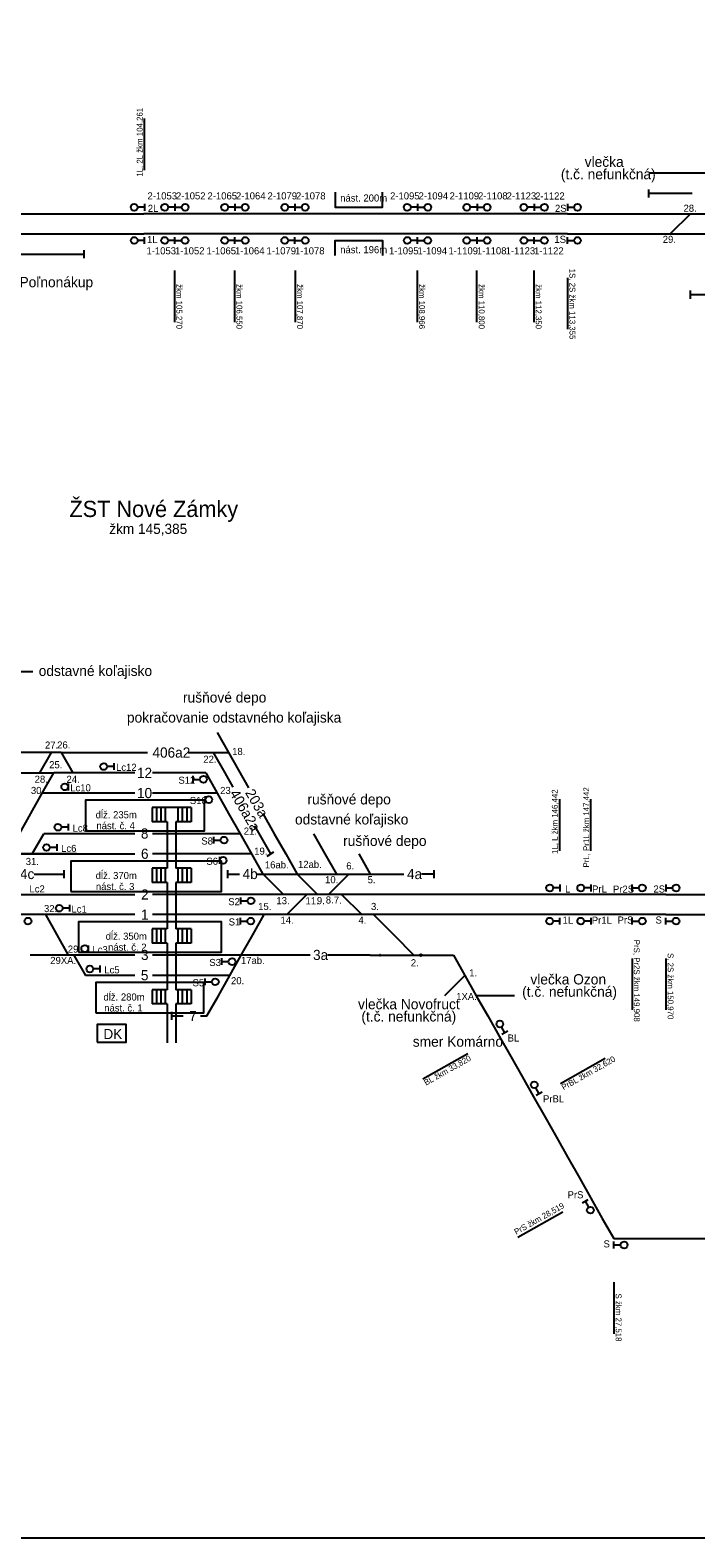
# Model space of a CAD drawing. Extents: x -119 to 851, y -238 to 59.
# Drawn here: x -13.2 to 52.5, y -238 to -89.2 of the extents above; entities that cross this region are included whole.
import ezdxf

# ---------------------------------------------------------------- set-up
doc = ezdxf.new("R2010")
doc.units = 0
for name, color, linetype in [('budova', 7, 'Continuous'), ('Level 2', 7, 'Continuous'), ('nastupistia', 7, 'Continuous'), ('netlač', 7, 'Continuous'), ('popisky navestidla', 7, 'Continuous'), ('popisky stanic a zastavok', 7, 'Continuous'), ('PU_navestidla', 7, 'Continuous'), ('PU_oznacenie navestidiel', 7, 'Continuous'), ('PU_podchod', 7, 'Continuous'), ('PU_stan_kolaje', 7, 'Continuous'), ('PU_vlecky', 7, 'Continuous'), ('schema_km0-1_0-2', 7, 'Continuous')]:
    doc.layers.add(name, color=color, linetype=linetype)

msp = doc.modelspace()

# ---------------------------------------------------------------- linework, layer by layer
at = {"layer": 'budova'}
msp.add_lwpolyline([(-6.62, -189.09), (-3.75, -189.09), (-3.75, -187.34), (-6.62, -187.34)], close=True, dxfattribs=at)
at = {"layer": 'Level 2'}
for p, q in [((53.81, -103.31), (47.81, -103.31)), ((47.81, -105.71), (47.81, -104.91)), ((52.09, -105.31), (47.81, -105.31)), ((-25.19, -107.3), (-1.99, -107.3)), ((39.78, -107.3), (51.39, -107.3)), ((51.39, -107.3), (67.59, -107.3)), ((-24.19, -109.3), (-5.89, -109.3)), ((-5.89, -109.3), (-1.99, -109.3)), ((39.78, -109.3), (66.39, -109.3)), ((-7.89, -111.7), (-7.89, -110.9)), ((51.92, -115.69), (51.92, -114.89)), ((-12.95, -152.51), (-19.77, -152.51)), ((-7.75, -168.5), (-10.45, -168.5)), ((-8.65, -170.5), (-14.55, -170.5)), ((10.17, -170.72), (10.83, -170.28)), ((-12.82, -172.49), (-9.86, -172.49)), ((-9.86, -172.89), (-9.86, -172.09)), ((6.3, -172.89), (6.3, -172.09)), ((6.3, -172.49), (7.43, -172.49)), ((9.15, -172.49), (9.78, -172.49)), ((9.78, -172.49), (23.65, -172.49)), ((26.64, -172.89), (26.64, -172.09)), ((-26.49, -174.49), (-2.88, -174.49)), ((49.49, -174.49), (59.31, -174.49)), ((49.49, -176.49), (74.3, -176.49)), ((0.75, -186.88), (0.75, -186.08)), ((0.75, -186.48), (1.88, -186.48)), ((3.6, -186.48), (4.22, -186.48)), ((44.36, -208.47), (49.06, -208.47)), ((46.08, -208.47), (50.14, -208.47)), ((49.06, -208.47), (64.03, -208.47))]:
    msp.add_line(p, q, dxfattribs=at)
at = {"layer": 'nastupistia'}
for points in [[(16.89, -105.17), (16.89, -106.67), (21.53, -106.67), (21.53, -105.17)], [(16.89, -111.44), (16.89, -109.94), (21.53, -109.94), (21.53, -111.44)]]:
    msp.add_lwpolyline(points, dxfattribs=at)
for points in [[(-7.74, -168.21), (3.98, -168.21), (3.98, -165.2), (-7.74, -165.2)], [(-9.2, -174.2), (5.65, -174.2), (5.65, -171.2), (-9.2, -171.2)], [(-8.43, -180.2), (5.65, -180.2), (5.65, -177.19), (-8.43, -177.19)], [(-6.72, -186.19), (3.91, -186.19), (3.91, -183.19), (-6.72, -183.19)]]:
    msp.add_lwpolyline(points, close=True, dxfattribs=at)
at = {"layer": 'netlač'}
for p, q in [((39.78, -107.3), (-1.99, -107.3)), ((39.78, -109.3), (-1.99, -109.3)), ((-17.22, -111.3), (-7.89, -111.3)), ((51.92, -115.29), (57.97, -115.29)), ((-10.15, -160.5), (-32.15, -160.5)), ((-10.15, -160.5), (-1.63, -160.5)), ((2.37, -160.5), (6.35, -160.5)), ((-15.74, -162.5), (-10.89, -162.5)), ((-2.88, -162.5), (-10.89, -162.5)), ((4.1, -162.5), (-1.16, -162.5)), ((-2.88, -164.5), (-12.02, -164.5)), ((5.23, -164.5), (-1.16, -164.5)), ((-2.88, -168.5), (-11.87, -168.5)), ((7.49, -168.5), (-1.16, -168.5)), ((-15.4, -170.5), (-2.88, -170.5)), ((8.62, -170.5), (-1.16, -170.5)), ((26.64, -172.49), (25.38, -172.49)), ((39.05, -174.49), (-1.16, -174.49)), ((49.49, -174.49), (39.05, -174.49)), ((-2.88, -176.49), (-26.56, -176.49)), ((9.87, -176.49), (-1.16, -176.49)), ((39.05, -176.49), (9.87, -176.49)), ((49.49, -176.49), (39.05, -176.49)), ((-9.45, -180.49), (-13.21, -180.49)), ((-2.88, -180.49), (-9.45, -180.49)), ((7.61, -180.49), (-1.16, -180.49)), ((14.41, -180.49), (7.61, -180.49)), ((20.33, -180.49), (16.13, -180.49)), ((20.33, -180.49), (28.54, -180.49)), ((-2.88, -182.49), (-7.77, -182.49)), ((6.48, -182.49), (-1.16, -182.49)), ((34.56, -184.49), (30.8, -184.49))]:
    msp.add_line(p, q, dxfattribs=at)
at = {"layer": 'popisky navestidla'}
for p, q in [((-1.94, -102.99), (-1.94, -97.9)), ((1.03, -112.9), (1.03, -118)), ((6.96, -112.9), (6.96, -118)), ((12.94, -112.9), (12.94, -118)), ((24.97, -112.9), (24.97, -118)), ((30.83, -112.9), (30.83, -118)), ((36.47, -112.9), (36.47, -118)), ((39.78, -113.62), (39.78, -118.71)), ((39.05, -170.18), (39.05, -165.09)), ((42.11, -170.18), (42.11, -165.09)), ((46.16, -180.81), (46.16, -185.9)), ((49.49, -180.81), (49.49, -185.9)), ((29.95, -190.22), (25.52, -192.73)), ((43.52, -190.68), (39.09, -193.18)), ((39.32, -205.85), (34.88, -208.36)), ((44.36, -212.78), (44.36, -217.87))]:
    msp.add_line(p, q, dxfattribs=at)
msp.add_lwpolyline([(-118.95, -238.01), (851.05, -238.01), (851.05, 58.99), (-118.95, 58.99)], close=True, dxfattribs=at)
at = {"layer": 'PU_navestidla'}
for p, q in [((-1.94, -106.67), (-2.62, -106.67)), ((-1.94, -106.33), (-1.94, -107)), ((1.07, -106.67), (0.39, -106.67)), ((1.07, -106.33), (1.07, -107.01)), ((1.07, -106.33), (1.07, -107.01)), ((1.07, -106.67), (1.74, -106.67)), ((6.99, -106.67), (6.32, -106.67)), ((6.99, -106.33), (6.99, -107.01)), ((6.99, -106.33), (6.99, -107.01)), ((6.99, -106.67), (7.66, -106.67)), ((12.91, -106.67), (12.24, -106.67)), ((12.91, -106.33), (12.91, -107.01)), ((12.91, -106.33), (12.91, -107.01)), ((12.91, -106.67), (13.58, -106.67)), ((25, -106.67), (24.33, -106.67)), ((25, -106.33), (25, -107.01)), ((25, -106.33), (25, -107.01)), ((25, -106.67), (25.67, -106.67)), ((30.87, -106.67), (30.19, -106.67)), ((30.87, -106.33), (30.87, -107.01)), ((30.87, -106.33), (30.87, -107.01)), ((30.87, -106.67), (31.54, -106.67)), ((36.5, -106.67), (35.83, -106.67)), ((36.5, -106.33), (36.5, -107.01)), ((36.5, -106.33), (36.5, -107.01)), ((36.5, -106.67), (37.17, -106.67)), ((39.78, -106.33), (39.78, -107)), ((39.78, -106.67), (40.45, -106.67)), ((-1.94, -109.94), (-2.62, -109.94)), ((-1.94, -110.28), (-1.94, -109.6)), ((1.07, -109.94), (0.39, -109.94)), ((1.07, -110.28), (1.07, -109.6)), ((1.07, -110.28), (1.07, -109.6)), ((1.07, -109.94), (1.74, -109.94)), ((6.99, -109.94), (6.32, -109.94)), ((6.99, -110.28), (6.99, -109.6)), ((6.99, -110.28), (6.99, -109.6)), ((6.99, -109.94), (7.66, -109.94)), ((12.91, -109.94), (12.24, -109.94)), ((12.91, -110.28), (12.91, -109.6)), ((12.91, -110.28), (12.91, -109.6)), ((12.91, -109.94), (13.58, -109.94)), ((25, -109.94), (24.33, -109.94)), ((25, -110.28), (25, -109.6)), ((25, -110.28), (25, -109.6)), ((25, -109.94), (25.67, -109.94)), ((30.87, -109.94), (30.19, -109.94)), ((30.87, -110.28), (30.87, -109.6)), ((30.87, -110.28), (30.87, -109.6)), ((30.87, -109.94), (31.54, -109.94)), ((36.5, -109.94), (35.83, -109.94)), ((36.5, -110.28), (36.5, -109.6)), ((36.5, -110.28), (36.5, -109.6)), ((36.5, -109.94), (37.17, -109.94)), ((39.78, -110.28), (39.78, -109.61)), ((39.78, -109.94), (40.45, -109.94)), ((-4.95, -161.87), (-5.62, -161.87)), ((-4.95, -161.53), (-4.95, -162.2)), ((-9.47, -163.55), (-9.47, -164.22)), ((2.87, -163.47), (2.87, -162.8)), ((2.87, -163.14), (3.54, -163.14)), ((4.08, -165.47), (4.08, -164.8)), ((-9.46, -167.86), (-10.13, -167.86)), ((-9.46, -167.53), (-9.46, -168.2)), ((-10.59, -169.52), (-10.59, -170.2)), ((4.9, -169.47), (4.9, -168.8)), ((4.9, -169.13), (5.57, -169.13)), ((-10.59, -169.86), (-11.26, -169.86)), ((5.49, -171.47), (5.49, -170.8)), ((39.05, -173.86), (38.37, -173.86)), ((39.05, -173.52), (39.05, -174.19)), ((42.11, -173.86), (41.44, -173.86)), ((42.11, -173.52), (42.11, -174.19)), ((46.16, -174.19), (46.16, -173.52)), ((46.16, -173.85), (46.83, -173.85)), ((49.49, -173.52), (49.49, -174.19)), ((49.49, -173.86), (50.16, -173.86)), ((-9.34, -175.52), (-9.34, -176.19)), ((7.56, -175.47), (7.56, -174.79)), ((7.56, -175.13), (8.24, -175.13)), ((-9.34, -175.86), (-10.02, -175.86)), ((7.55, -177.46), (7.55, -176.79)), ((39.05, -177.46), (39.05, -176.79)), ((42.11, -176.8), (42.11, -177.47)), ((46.16, -177.47), (46.16, -176.79)), ((49.49, -177.47), (49.49, -176.79)), ((7.55, -177.13), (8.22, -177.13)), ((39.05, -177.13), (38.37, -177.13)), ((42.11, -177.13), (41.44, -177.13)), ((46.16, -177.13), (46.83, -177.13)), ((49.49, -177.13), (50.16, -177.13)), ((-7.5, -179.52), (-7.5, -180.19)), ((-6.33, -181.51), (-6.33, -182.19)), ((5.69, -181.46), (5.69, -180.79)), ((5.69, -181.13), (6.36, -181.13)), ((-6.33, -181.85), (-7, -181.85)), ((4.05, -183.46), (4.05, -182.79)), ((4.05, -183.12), (4.72, -183.12)), ((33.62, -188.17), (33.29, -187.58)), ((33.91, -188), (33.32, -188.33)), ((37.01, -194.17), (36.68, -193.58)), ((37.3, -194), (36.71, -194.33)), ((41.26, -204.95), (41.84, -204.62)), ((41.55, -204.78), (41.88, -205.37)), ((44.36, -209.44), (44.36, -208.77)), ((44.36, -209.1), (45.04, -209.1))]:
    msp.add_line(p, q, dxfattribs=at)
for centre in [(-2.95, -106.67), (0.06, -106.67), (2.07, -106.67), (5.98, -106.67), (8, -106.67), (11.9, -106.67), (13.92, -106.67), (23.99, -106.67), (26.01, -106.67), (29.86, -106.67), (31.87, -106.67), (35.49, -106.67), (37.51, -106.67), (40.78, -106.67), (-2.95, -109.94), (0.06, -109.94), (2.07, -109.94), (5.98, -109.94), (8, -109.94), (11.9, -109.94), (13.92, -109.94), (23.99, -109.94), (26.01, -109.94), (29.86, -109.94), (31.87, -109.94), (35.49, -109.94), (37.51, -109.94), (40.78, -109.94), (-5.96, -161.87), (-9.8, -163.88), (3.87, -163.14), (4.41, -165.14), (-10.47, -167.86), (-11.6, -169.86), (5.91, -169.13), (5.82, -171.13), (38.04, -173.86), (41.1, -173.86), (47.17, -173.86), (50.5, -173.86), (-10.35, -175.86), (8.57, -175.13), (-13.43, -177.13), (8.55, -177.13), (38.04, -177.13), (41.1, -177.13), (47.17, -177.13), (50.5, -177.13), (-7.83, -179.85), (-7.33, -181.85), (6.7, -181.13), (5.05, -183.12), (33.12, -187.29), (36.51, -193.29), (42.05, -205.66), (45.37, -209.1)]:
    msp.add_circle(centre, 0.336, dxfattribs=at)
at = {"layer": 'PU_podchod'}
for p, q in [((-1.18, -165.91), (-1.18, -167.32)), ((0.31, -165.91), (-1.18, -165.91)), ((-0.75, -165.91), (-0.75, -167.32)), ((-0.32, -165.91), (-0.32, -167.32)), ((0.12, -165.91), (0.12, -167.32)), ((2.66, -165.91), (0.31, -165.91)), ((1.36, -165.91), (1.36, -167.32)), ((1.79, -165.91), (1.79, -167.32)), ((2.23, -165.91), (2.23, -167.32)), ((2.66, -165.91), (2.66, -167.32)), ((0.31, -167.32), (-1.18, -167.32)), ((0.31, -167.32), (0.31, -171.91)), ((1.17, -167.32), (1.17, -171.91)), ((2.66, -167.32), (1.17, -167.32)), ((-1.18, -171.91), (-1.18, -173.31)), ((0.31, -171.91), (-1.18, -171.91)), ((-0.75, -171.91), (-0.75, -173.31)), ((-0.32, -171.91), (-0.32, -173.31)), ((0.12, -171.91), (0.12, -173.31)), ((2.66, -171.91), (1.17, -171.91)), ((1.36, -171.91), (1.36, -173.31)), ((1.79, -171.91), (1.79, -173.31)), ((2.23, -171.91), (2.23, -173.31)), ((2.66, -171.91), (2.66, -173.31)), ((0.31, -173.31), (-1.18, -173.31)), ((0.31, -173.31), (0.31, -177.9)), ((2.66, -173.31), (1.17, -173.31)), ((1.17, -173.31), (1.17, -177.9)), ((-1.18, -177.9), (-1.18, -179.31)), ((0.31, -177.9), (-1.18, -177.9)), ((-0.75, -177.9), (-0.75, -179.31)), ((-0.32, -177.9), (-0.32, -179.31)), ((0.12, -177.9), (0.12, -179.31)), ((2.66, -177.9), (1.17, -177.9)), ((1.36, -177.9), (1.36, -179.31)), ((1.79, -177.9), (1.79, -179.31)), ((2.23, -177.9), (2.23, -179.31)), ((2.66, -177.9), (2.66, -179.31)), ((0.31, -179.31), (-1.18, -179.31)), ((0.31, -179.31), (0.31, -183.9)), ((2.66, -179.31), (1.17, -179.31)), ((1.17, -179.31), (1.17, -183.9)), ((0.31, -183.9), (-1.18, -183.9)), ((-1.18, -183.9), (-1.18, -185.3)), ((-0.75, -183.9), (-0.75, -185.3)), ((-0.32, -183.9), (-0.32, -185.3)), ((0.12, -183.9), (0.12, -185.3)), ((2.66, -183.9), (1.17, -183.9)), ((1.36, -183.9), (1.36, -185.3)), ((1.79, -183.9), (1.79, -185.3)), ((2.23, -183.9), (2.23, -185.3)), ((2.66, -183.9), (2.66, -185.3)), ((0.31, -185.3), (-1.18, -185.3)), ((0.31, -185.3), (0.31, -189.15)), ((2.66, -185.3), (1.17, -185.3)), ((1.17, -185.3), (1.17, -189.15))]:
    msp.add_line(p, q, dxfattribs=at)
at = {"layer": 'PU_stan_kolaje'}
for p, q in [((6.36, -160.5), (8.32, -163.98)), ((5.98, -162.5), (6.77, -163.9)), ((8.93, -167.71), (10.5, -170.5))]:
    msp.add_line(p, q, dxfattribs=at)
for points in [[(51.92, -107.3), (49.93, -109.3)], [(5.23, -158.51), (6.36, -160.5)], [(-12.25, -162.5), (-11.12, -160.5)], [(-10.15, -160.5), (-9.02, -162.5)], [(4.85, -160.5), (5.98, -162.5)], [(-12.02, -164.5), (-10.89, -162.5)], [(4.1, -162.5), (5.23, -164.5)], [(-13.15, -166.5), (-12.02, -164.5)], [(5.23, -164.5), (6.36, -166.5)], [(-14.28, -168.5), (-13.15, -166.5)], [(6.36, -166.5), (7.49, -168.5)], [(9.75, -166.5), (10.87, -168.5)], [(-13, -170.5), (-11.87, -168.5)], [(7.49, -168.5), (8.62, -170.5)], [(10.87, -168.5), (12, -170.5)], [(14.74, -168.5), (15.87, -170.5)], [(8.62, -170.5), (9.75, -172.49)], [(12, -170.5), (13.13, -172.49)], [(15.87, -170.5), (17, -172.49)], [(19.21, -170.5), (20.34, -172.49)], [(9.78, -172.49), (11.78, -174.49)], [(13.13, -172.49), (15.13, -174.49)], [(18.21, -172.49), (16.21, -174.49)], [(14.09, -174.49), (12.09, -176.49)], [(17.49, -174.49), (19.49, -176.49)], [(-11.71, -176.49), (-10.58, -178.49)], [(8.74, -178.49), (9.87, -176.49)], [(20.65, -176.49), (22.65, -178.49)], [(-10.58, -178.49), (-9.45, -180.49)], [(7.61, -180.49), (8.74, -178.49)], [(22.65, -178.49), (24.65, -180.49)], [(-8.9, -180.49), (-7.77, -182.49)], [(6.48, -182.49), (7.61, -180.49)], [(28.54, -180.49), (29.67, -182.49)], [(5.35, -184.49), (6.48, -182.49)], [(29.67, -182.49), (27.67, -184.49)], [(29.67, -182.49), (30.8, -184.49)], [(4.22, -186.48), (5.35, -184.49)], [(30.8, -184.49), (31.93, -186.48)], [(31.93, -186.48), (33.06, -188.48)], [(33.06, -188.48), (34.19, -190.48)], [(34.19, -190.48), (35.32, -192.48)], [(35.32, -192.48), (36.45, -194.48)], [(36.45, -194.48), (37.58, -196.48)], [(37.58, -196.48), (38.71, -198.47)], [(38.71, -198.47), (39.84, -200.47)], [(39.84, -200.47), (40.97, -202.47)], [(40.97, -202.47), (42.1, -204.47)], [(42.1, -204.47), (43.23, -206.47)], [(43.23, -206.47), (44.36, -208.47)]]:
    msp.add_lwpolyline(points, dxfattribs=at)
at = {"layer": 'schema_km0-1_0-2'}
for centre, radius in [((21.32, -180.49), 0.0502), ((25.32, -180.49), 0.1)]:
    msp.add_circle(centre, radius, dxfattribs=at)

# ---------------------------------------------------------------- texts
at = {"layer": 'budova'}
msp.add_text('DK', height=1.004, dxfattribs=at).set_placement((-5.99, -188.78))
at = {"layer": 'nastupistia'}
for s, p in [('nást. 200m', (17.37, -106.1)), ('nást. 196m', (17.37, -111.2)), ('dĺž. 235m', (-6.75, -166.98)), ('nást. č. 4', (-6.68, -168.06)), ('dĺž. 370m', (-6.75, -172.98)), ('nást. č. 3', (-6.73, -174.06)), ('dĺž. 350m', (-5.76, -178.97)), ('nást. č. 2', (-5.53, -180.05)), ('dĺž. 280m', (-5.98, -184.97)), ('nást. č. 1', (-5.91, -186.05))]:
    msp.add_text(s, height=0.7, dxfattribs=at).set_placement(p)
at = {"layer": 'popisky navestidla'}
for s, rotation, p in [('1L, 2L žkm 104,261', 90, (-2.12, -103.65)), ('1S, 2S žkm 113,355', 270, (39.99, -112.73)), ('žkm 105,270', 270, (1.21, -114.25)), ('žkm 106,550', 270, (7.14, -114.25)), ('žkm 107,870', 270, (13.11, -114.25)), ('žkm 108,966', 270, (25.15, -114.25)), ('žkm 110,800', 270, (31.04, -114.25)), ('žkm 112,350', 270, (36.65, -114.25)), ('1L, L žkm 146,442', 90, (38.83, -170.5)), ('PrL, Pr1L žkm 147,442', 90, (41.93, -171.84)), ('PrS, Pr2S žkm 149,908', 270, (46.34, -178.97)), ('S, 2S žkm 150,970', 270, (49.67, -180.28)), ('BL žkm 33,820', 29.4841, (25.84, -193.38)), ('PrBL žkm 32,620', 29.4841, (39.41, -193.84)), ('PrS žkm 28,519', 29.4841, (34.74, -208.11)), ('S žkm 27,518', 270, (44.54, -213.89))]:
    msp.add_text(s, height=0.5793, rotation=rotation, dxfattribs=at).set_placement(p)
at = {"layer": 'popisky stanic a zastavok'}
for s, height, p in [('ŽST Nové Zámky', 1.6, (-9.34, -137.24)), ('žkm 145,385', 1.0044, (-5.41, -138.91))]:
    msp.add_text(s, height=height, dxfattribs=at).set_placement(p)
at = {"layer": 'PU_oznacenie navestidiel'}
for s, p in [('2-1053', (-1.64, -105.89)), ('2-1052', (1.17, -105.89)), ('2-1065', (4.28, -105.89)), ('2-1064', (7.09, -105.89)), ('2-1079', (10.2, -105.89)), ('2-1078', (13.01, -105.89)), ('2-1095', (22.29, -105.89)), ('2-1094', (25.1, -105.89)), ('2-1109', (28.16, -105.89)), ('2-1108', (30.97, -105.89)), ('2-1123', (33.79, -105.89)), ('2-1122', (36.6, -105.9)), ('2L', (-1.61, -107.12)), ('2S', (38.56, -107.12)), ('28.', (51.24, -107.11)), ('1L', (-1.68, -110.19)), ('1S', (38.5, -110.18)), ('29.', (49.19, -110.18)), ('1-1053', (-1.74, -111.31)), ('1-1052', (1.07, -111.31)), ('1-1065', (4.18, -111.31)), ('1-1064', (6.99, -111.31)), ('1-1079', (10.1, -111.31)), ('1-1078', (12.91, -111.31)), ('1-1095', (22.19, -111.31)), ('1-1094', (25, -111.31)), ('1-1109', (28.05, -111.31)), ('1-1108', (30.86, -111.31)), ('1-1123', (33.69, -111.31)), ('1-1122', (36.5, -111.32)), ('27.', (-11.75, -160.1)), ('26.', (-10.55, -160.09)), ('18.', (6.71, -160.73)), ('25.', (-11.34, -162.04)), ('Lc12', (-4.74, -162.3)), ('22.', (3.87, -161.5)), ('28.', (-12.77, -163.47)), ('24.', (-9.63, -163.48)), ('Lc10', (-9.26, -164.32)), ('S12', (1.41, -163.57)), ('30.', (-13.14, -164.58)), ('S10', (2.54, -165.57)), ('23.', (5.53, -164.58)), ('Lc8', (-9.03, -168.3)), ('21.', (7.86, -168.59)), ('Lc6', (-10.16, -170.3)), ('S8', (3.67, -169.57)), ('31.', (-13.65, -171.59)), ('S6', (4.17, -171.57)), ('19.', (8.89, -170.57)), ('12ab.', (13.21, -171.88)), ('16ab.', (9.94, -171.92)), ('6.', (17.97, -172.03)), ('Lc2', (-13.28, -174.3)), ('10.', (15.88, -173.39)), ('5.', (20.08, -173.39)), ('L', (39.56, -174.31)), ('PrL', (42.22, -174.31)), ('Pr2S', (44.28, -174.32)), ('2S', (48.27, -174.31)), ('32.', (-11.85, -176.24)), ('Lc1', (-9.14, -176.29)), ('S2', (6.33, -175.56)), ('15.', (9.28, -176.03)), ('13.', (11.08, -175.46)), ('11.', (13.95, -175.47)), ('9.', (15.07, -175.46)), ('8.', (15.95, -175.39)), ('7.', (16.74, -175.41)), ('3.', (20.41, -176.03)), ('S1', (6.37, -177.56)), ('14.', (11.48, -177.38)), ('4.', (19.17, -177.38)), ('1L', (39.31, -177.38)), ('Pr1L', (42.19, -177.39)), ('PrS', (44.73, -177.37)), ('S', (48.48, -177.37)), ('29.', (-9.5, -180.24)), ('Lc3', (-7.07, -180.29)), ('29XA.', (-11.23, -181.36)), ('S3', (4.46, -181.56)), ('17ab.', (7.58, -181.36)), ('2.', (24.34, -181.59)), ('Lc5', (-5.9, -182.29)), ('S5', (2.81, -183.56)), ('20.', (6.6, -183.36)), ('1.', (30.09, -182.59)), ('1XA.', (28.82, -184.92)), ('BL  ', (33.89, -189.02)), ('PrBL  ', (37.38, -195.02)), ('PrS', (39.8, -204.49)), ('S', (43.35, -209.34))]:
    msp.add_text(s, height=0.7, dxfattribs=at).set_placement(p)
at = {"layer": 'PU_stan_kolaje'}
for s, height, p in [('406a2', 1.004, (-1.15, -160.99)), ('12', 1.004, (-2.68, -163)), ('10', 1.004, (-2.68, -164.99)), ('8', 1, (-2.29, -168.98)), ('6', 1, (-2.28, -170.98)), ('4c', 1.004, (-14.22, -172.98)), ('4b', 1.004, (7.74, -172.98)), ('4a', 1.004, (23.96, -172.98)), ('2', 1, (-2.27, -175)), ('1', 1, (-2.28, -176.99)), ('3', 1, (-2.28, -180.97)), ('3a', 1.004, (14.69, -180.97)), ('5', 1, (-2.29, -182.97)), ('7', 1, (2.47, -186.99))]:
    msp.add_text(s, height=height, dxfattribs=at).set_placement(p)
for s, p in [('406a2a', (6.43, -164.51)), ('203a', (7.96, -164.45))]:
    msp.add_text(s, height=1.004, rotation=300.1422, dxfattribs=at).set_placement(p)
at = {"layer": 'PU_vlecky'}
for s, p in [('vlečka', (41.49, -102.68)), ('(t.č. nefunkčná)', (39.14, -103.9)), ('vlečka Poľnonákup', (-18.49, -114.56)), ('odstavné koľajisko', (-12.37, -152.93)), ('rušňové depo', (1.86, -155.55)), ('pokračovanie odstavného koľajiska', (-3.67, -157.53)), ('rušňové depo', (14.14, -165.61)), ('odstavné koľajisko', (12.91, -167.59)), ('rušňové depo', (17.66, -169.71)), ('vlečka Ozon', (36.13, -183.38)), ('(t.č. nefunkčná)', (35.32, -184.6)), ('vlečka Novofruct', (19.13, -185.83)), ('(t.č. nefunkčná)', (19.46, -187.04)), ('smer Komárno', (24.53, -189.53))]:
    msp.add_text(s, height=1.015, dxfattribs=at).set_placement(p)

doc.saveas('drawing.dxf')
